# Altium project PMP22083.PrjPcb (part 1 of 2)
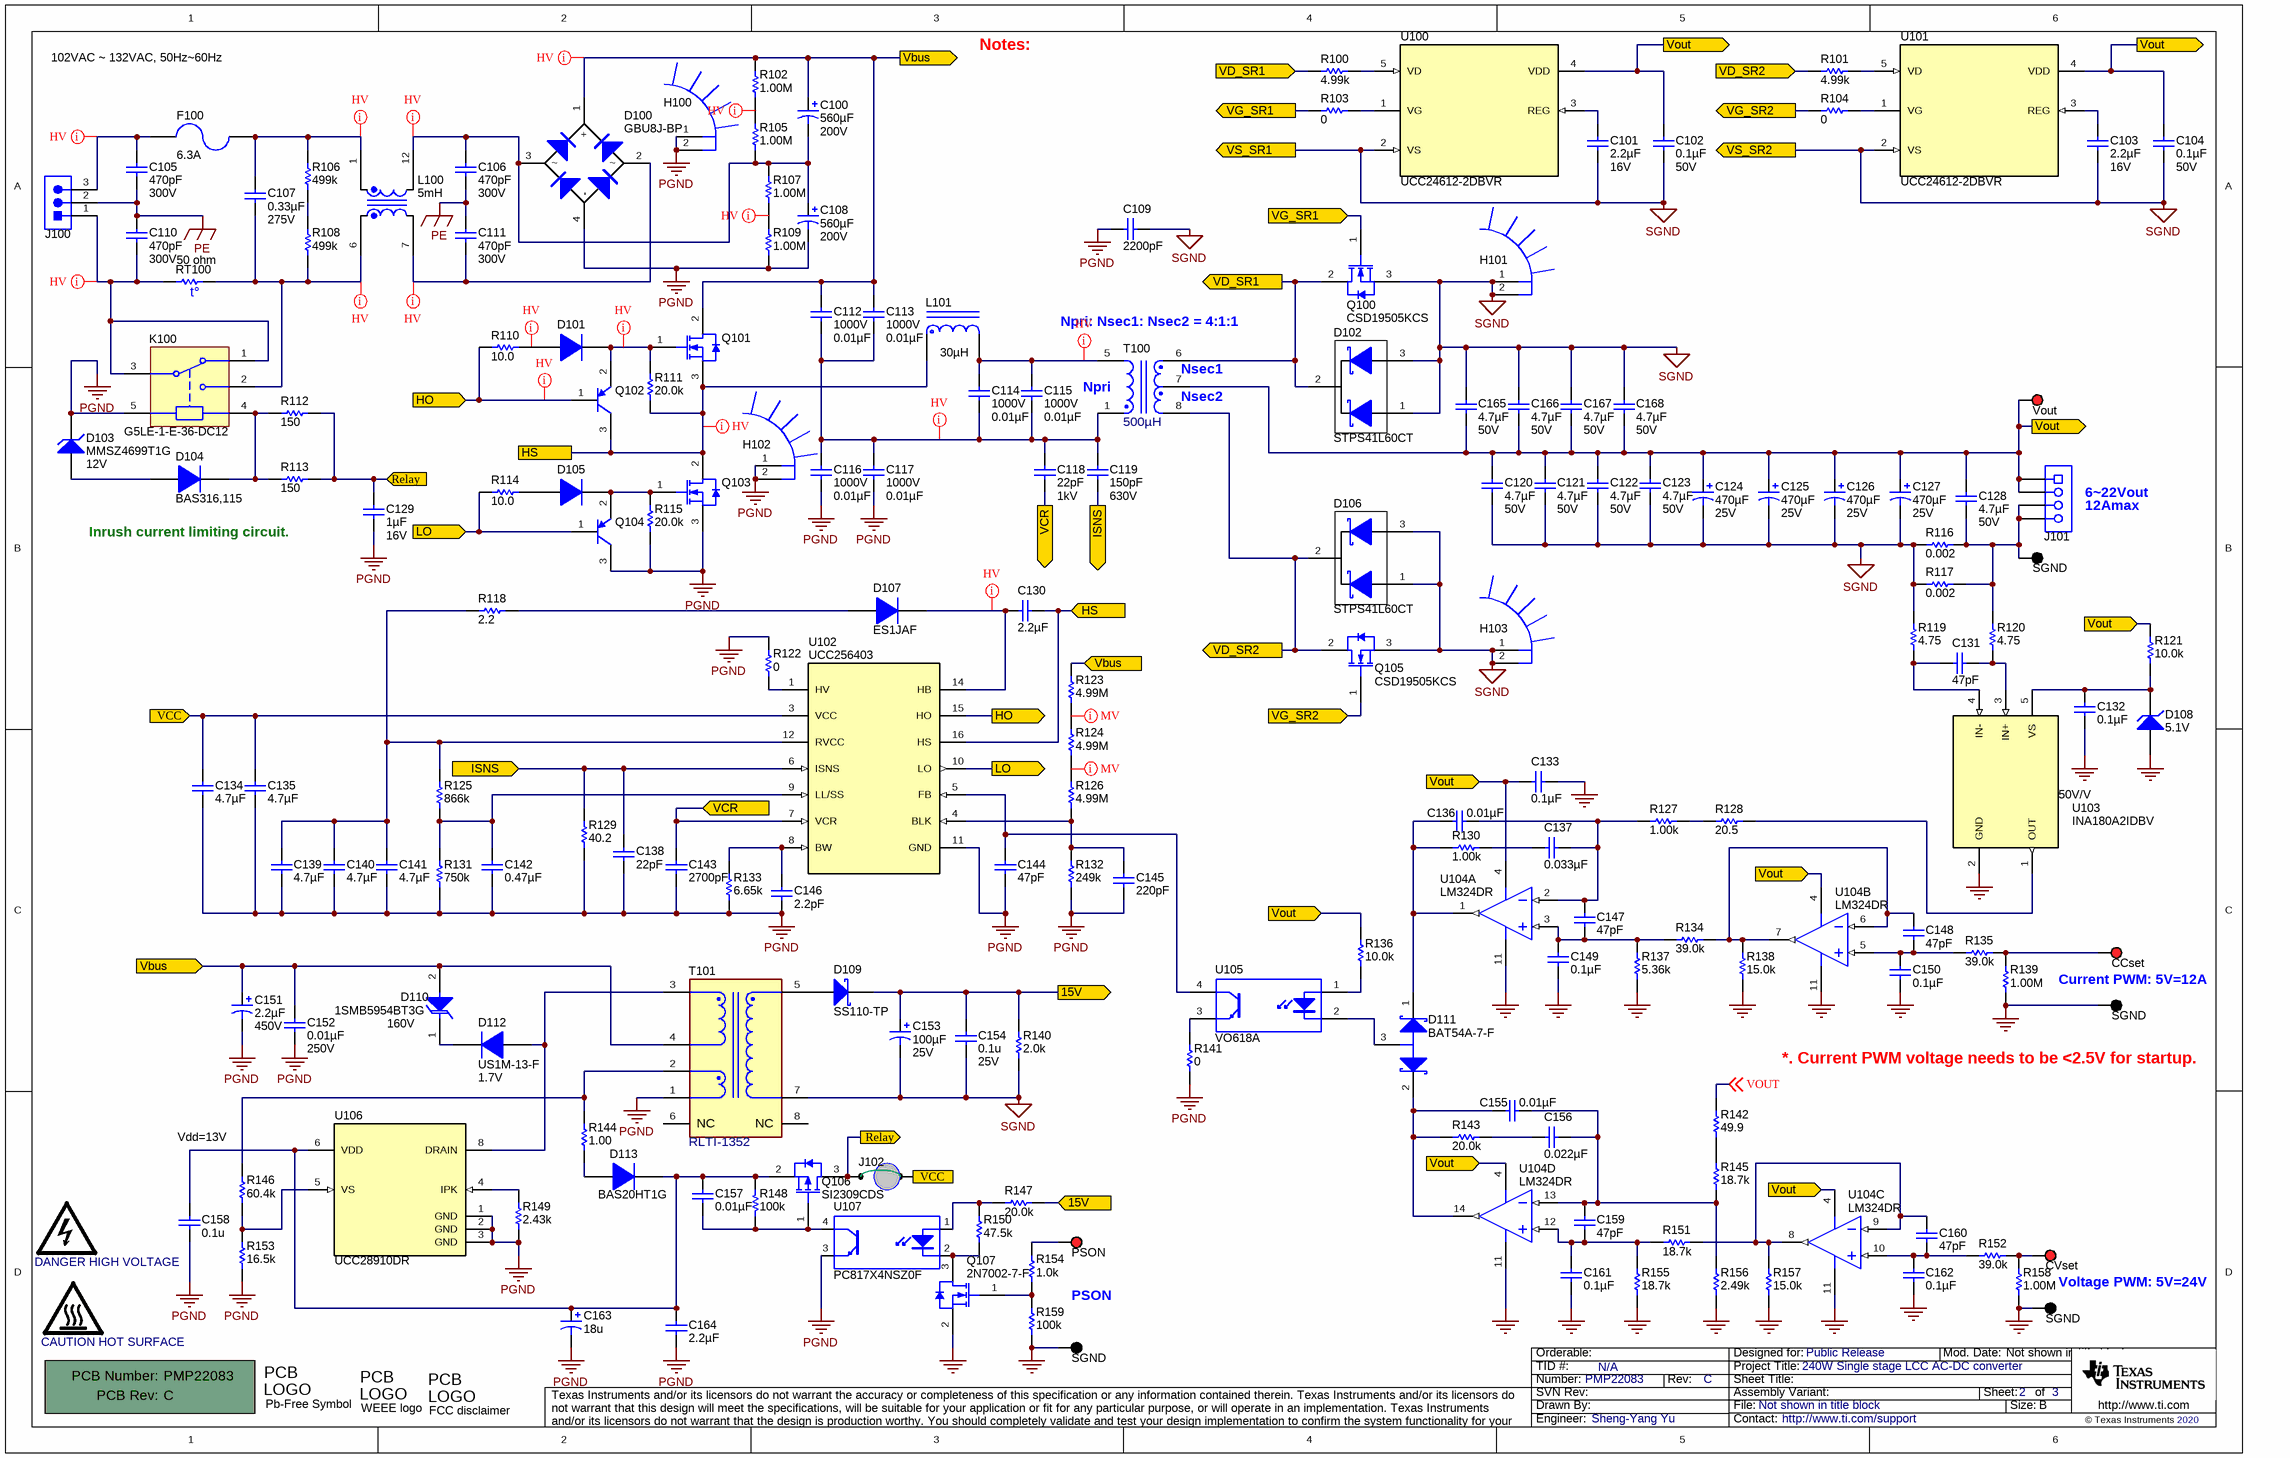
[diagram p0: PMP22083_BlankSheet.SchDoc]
CopyrightYear: 2020; PCB_Layout: Sheng-Yang Yu; PCB_Rev: C; PRJ_Customer: Public Release; PRJ_Engineer: Sheng-Yang Yu; PRJ_Number: PMP22083; PRJ_Title: 240W Single stage LCC AC-DC converter; SCH_Rev: C; TechSupport: http://www.ti.com/support; TID: N/A
1 sheet, 187 parts. Net scope: flat (ports and power ports of the same name join across sheets).
Board file: PMP22083_PCB.PcbDoc

## Sheet PMP22083_BlankSheet.SchDoc
size 431 x 279 mm; Date: Not shown in title block; ApprovedBy: Not shown in title block; CheckedBy: Not shown in title block; Author: Not shown in title block; CompanyName: Not shown in title block; Engineer: Not shown in title block; Organization: Not shown in title block; Address1: Not shown in title block; Address2: Not shown in title block; Address3: Not shown in title block; Address4: Not shown in title block; DocumentNumber: 1; Revision: Use project parameter SCH_Rev; SheetNumber: 2; SheetTotal: 3; PageSetup: Record=PageOptions¦CenterHorizontal=True¦CenterVertical=True¦PrintScale=1.00¦XCorrection=1.00¦YCorrection=1.00¦PrintKind=0¦BorderSize=5000000¦LeftOffset=0¦BottomOffset=0¦Orientation=2¦PaperLength=1000¦PaperWidth=1000¦Scale=100¦PaperSource=15¦PrintQuality=600¦MediaType=1¦DitherType=10¦PaperKind=Letter¦PrintScaleMode=1

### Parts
(Parts that share a designator on the sheet are numbered #1, #2 ... from top to bottom, then left to right.)
!PCB100  Printed Circuit Board  (value not drawn)  (mechanical)
C100  Cap_F: 560µF  VDC_V: 200V  [Nichicon_2200x3000_Snap]  (hidden comment: LLS2W101MELZ)
C101  ValueDisplayed: 2.2µF  Value2: 16V  [0603]  (hidden comment: 885012106018)
C102  ValueDisplayed: 0.1µF  Value2: 50V  [0603]  (hidden comment: 885012206095)
C103  ValueDisplayed: 2.2µF  Value2: 16V  [0603]  (hidden comment: 885012106018)
C104  ValueDisplayed: 0.1µF  Value2: 50V  [0603]  (hidden comment: 885012206095)
C105  ValueDisplayed: 470pF  Value2: 300V  [VY2_750x500]  (hidden comment: VY2471K29Y5SS63V7)
C106  ValueDisplayed: 470pF  Value2: 300V  [VY2_750x500]  (hidden comment: VY2471K29Y5SS63V7)
C107  ValueDisplayed: 0.33µF  Value2: 275V  [CAPRR1500W80L1750T950H1750]  (hidden comment: ECQ-U2A334ML)
C108  Cap_F: 560µF  VDC_V: 200V  [Nichicon_2200x3000_Snap]  (hidden comment: LLS2W101MELZ)
C109  ValueDisplayed: 2200pF  [AY2_950x500_Straight]  (hidden comment: AY2222M35Y5US63L7)
C110  ValueDisplayed: 470pF  Value2: 300V  [VY2_750x500]  (hidden comment: VY2471K29Y5SS63V7)
C111  ValueDisplayed: 470pF  Value2: 300V  [VY2_750x500]  (hidden comment: VY2471K29Y5SS63V7)
C112  VDC_V: 1000V  ValueDisplayed: 0.01µF  [B32621_1300x600x1200]  (hidden comment: B32671L0103J000)
C113  VDC_V: 1000V  ValueDisplayed: 0.01µF  [B32621_1300x600x1200]  (hidden comment: B32671L0103J000)
C114  VDC_V: 1000V  ValueDisplayed: 0.01µF  [B32621_1300x600x1200]  (hidden comment: B32671L0103J000)
C115  VDC_V: 1000V  ValueDisplayed: 0.01µF  [B32621_1300x600x1200]  (hidden comment: B32671L0103J000)
C116  VDC_V: 1000V  ValueDisplayed: 0.01µF  [B32621_1300x600x1200]  (hidden comment: B32671L0103J000)
C117  VDC_V: 1000V  ValueDisplayed: 0.01µF  [B32621_1300x600x1200]  (hidden comment: B32671L0103J000)
C118  ValueDisplayed: 22pF  Value2: 1kV  [1206]  (hidden comment: VJ1206A220JXGAT5Z)
C119  ValueDisplayed: 150pF  Value2: 630V  [1206]  (hidden comment: GRM31A5C2J151JW01D)
C120  ValueDisplayed: 4.7µF  Value2: 50V  [1206_190]  (hidden comment: UMK316AB7475KL-T)
C121  ValueDisplayed: 4.7µF  Value2: 50V  [1206_190]  (hidden comment: UMK316AB7475KL-T)
C122  ValueDisplayed: 4.7µF  Value2: 50V  [1206_190]  (hidden comment: UMK316AB7475KL-T)
C123  ValueDisplayed: 4.7µF  Value2: 50V  [1206_190]  (hidden comment: UMK316AB7475KL-T)
C124  ValueDisplayed: 470µF  Value2: 25V  [FR_1000x2000]  (hidden comment: 25SEK470M)
C125  ValueDisplayed: 470µF  Value2: 25V  [FR_1000x2000]  (hidden comment: 25SEK470M)
C126  ValueDisplayed: 470µF  Value2: 25V  [FR_1000x2000]  (hidden comment: 25SEK470M)
C127  ValueDisplayed: 470µF  Value2: 25V  [FR_1000x2000]  (hidden comment: 25SEK470M)
C128  ValueDisplayed: 4.7µF  Value2: 50V  [1206_190]  (hidden comment: UMK316AB7475KL-T)
C129  ValueDisplayed: 1µF  Value2: 16V  [0805_HV]  (hidden comment: 0805YD105KAT2A)
C130  ValueDisplayed: 2.2µF  [1206]  (hidden comment: C1206C225K4RACTU)
C131  ValueDisplayed: 47pF  [0603]  (hidden comment: C0603C470J5GACTU)
C132  ValueDisplayed: 0.1µF  [0402]  (hidden comment: GRM155R61E104KA87D)
C133  ValueDisplayed: 0.1µF  [1206]  (hidden comment: C1206C104K5RACTU)
C134  ValueDisplayed: 4.7µF  [0603]  (hidden comment: GRM188R61C475KAAJ)
C135  ValueDisplayed: 4.7µF  [0603]  (hidden comment: GRM188R61C475KAAJ)
C136  ValueDisplayed: 0.01µF  [0402]  (hidden comment: GRM155R71H103KA88D)
C137  ValueDisplayed: 0.033µF  [0402]  (hidden comment: GRM155R61C333KA01D)
C138  ValueDisplayed: 22pF  [0603]  (hidden comment: 06035A220JAT2A)
C139  ValueDisplayed: 4.7µF  [0603]  (hidden comment: GRM188R61C475KAAJ)
C140  ValueDisplayed: 4.7µF  [0603]  (hidden comment: GRM188R61C475KAAJ)
C141  ValueDisplayed: 4.7µF  [0603]  (hidden comment: GRM188R61C475KAAJ)
C142  ValueDisplayed: 0.47µF  [0603]  (hidden comment: C0603C474Z8VACTU)
C143  ValueDisplayed: 2700pF  [0603]  (hidden comment: GRM188R71E272KA01D)
C144  ValueDisplayed: 47pF  [0603]  (hidden comment: GRM1885C1H470FA01J)
C145  ValueDisplayed: 220pF  [0603]  (hidden comment: GRM188R71H221KA01D)
C146  ValueDisplayed: 2.2pF  [0603]  (hidden comment: 06035A2R2CAT2A)
C147  ValueDisplayed: 47pF  [0603]  (hidden comment: GRM1885C1H470JA01D)
C148  ValueDisplayed: 47pF  [0603]  (hidden comment: GRM1885C1H470JA01D)
C149  ValueDisplayed: 0.1µF  [0805_HV]  (hidden comment: 08053C104JAT2A)
C150  ValueDisplayed: 0.1µF  [0805_HV]  (hidden comment: 08053C104JAT2A)
C151  ValueDisplayed: 2.2µF  Value2: 450V  [CKE_800x1150]  (hidden comment: 225CKE450MJM)
C152  ValueDisplayed: 0.01µF  Value2: 250V  [1206]  (hidden comment: C1206C103KARACTU)
C153  ValueDisplayed: 100µF  Value2: 25V  [NHG_630x1120]  (hidden comment: ECA-1EHG101)
C154  ValueDisplayed: 0.1u  Value2: 25V  [0805_HV]  (hidden comment: 08053C104KAT2A)
C155  ValueDisplayed: 0.01µF  [0402]  (hidden comment: GRM155R71H103KA88D)
C156  ValueDisplayed: 0.022µF  [0402]  (hidden comment: GCM155R71H223KA55D)
C157  ValueDisplayed: 0.01µF  [0603]  (hidden comment: 885012206040)
C158  ValueDisplayed: 0.1u  [0603]  (hidden comment: 06035C104KAT2A)
C159  ValueDisplayed: 47pF  [0402]  (hidden comment: GRM1555C1H470JA01D)
C160  ValueDisplayed: 47pF  [0603]  (hidden comment: GRM1885C1H470JA01D)
C161  ValueDisplayed: 0.1µF  [0603]  (hidden comment: 06035C104KAT2A)
C162  ValueDisplayed: 0.1µF  [0603]  (hidden comment: 06035C104KAT2A)
C163  ValueDisplayed: 18u  [ML_500x500]  (hidden comment: 35ZL18MEFC5X7)
C164  ValueDisplayed: 2.2µF  [0603]  (hidden comment: GRM188R6YA225KA12D)
C165  ValueDisplayed: 4.7µF  Value2: 50V  [1206_190]  (hidden comment: UMK316AB7475KL-T)
C166  ValueDisplayed: 4.7µF  Value2: 50V  [1206_190]  (hidden comment: UMK316AB7475KL-T)
C167  ValueDisplayed: 4.7µF  Value2: 50V  [1206_190]  (hidden comment: UMK316AB7475KL-T)
C168  ValueDisplayed: 4.7µF  Value2: 50V  [1206_190]  (hidden comment: UMK316AB7475KL-T)
CCset  5000  [Keystone5000]  (value not drawn)
CVset  5000  [Keystone5000]  (value not drawn)
D100  GBU8J-BP  [GBU]
D101  MMDL914-TP  [SOD-323]  (value not drawn)
D102  STPS41L60CT  [TO-220AB]
D103  MMSZ4699T1G  value 12V  [SOD-123]
D104  BAS316,115  [sod-323]
D105  MMDL914-TP  [SOD-323]  (value not drawn)
D106  STPS41L60CT  [TO-220AB]
D107  ES1JAF  [SMAF]
D108  value 5.1V  [SOD-323]  (hidden comment: MMSZ5231BS-7-F)
D109  SS110-TP  [SMA]
D110  1SMB5954BT3G  value 160V  [SMB]
D111  BAT54A-7-F  [SOT-23]
D112  US1M-13-F  value 1.7V  [SMA]
D113  BAS20HT1G  [sod-323]
F100  Irating_A: 6.3A  [FUSE_372]  (hidden comment: 37216300001)
H100  532602B02500G  [Aavid_532602B02500G]  (value not drawn)
H101  513302B02500G  [531202]  (value not drawn)
H102  513302B02500G  [531202]  (value not drawn)
H103  513302B02500G  [531202]  (value not drawn)
J100  1-1318301-3  [TE_1-1318301-3]  (value not drawn)
J101  ED120/4DS  [On-Shore_ED120_4DS]  (value not drawn)
J102  923345-05-C  [923345-05-C]  (value not drawn)
K100  G5LE-1-E-36-DC12  [RELAY_875]
L100  ValueDisplayed: 5mH  [WE-CMB_XL]  (hidden comment: 744825605)
L101  Ind_H: 30µH  [FP-61219_SMT_36MM0_34MM0-MFG]  (hidden comment: 61219)
LOGO100  DANGER HIGH VOLTAGE  [IEC_HighVoltage_Small]  (no BOM)
LOGO101  CAUTION HOT SURFACE  [IEC_HotSurface_Small]  (no BOM)
Logo102  Pb-Free Symbol  [Pb-Free_Overlay_Medium]  (no BOM)
Logo103  WEEE logo  [WEEE_Minimum]  (no BOM)
Logo104  FCC disclaimer  [FCC_disclaimer]  (no BOM)
PSON  5000  [Keystone5000]  (value not drawn)
Q100  CSD19505KCS  [KCS0003B]
Q101  IPP60R090CFD7XKSA1  [TO-220FP]  (value not drawn)
Q102  FMMT718TA  [SOT-23]  (value not drawn)
Q103  IPP60R090CFD7XKSA1  [TO-220FP]  (value not drawn)
Q104  FMMT718TA  [SOT-23]  (value not drawn)
Q105  CSD19505KCS  [KCS0003B]
Q106  SI2309CDS  [SOT-23]
Q107  2N7002-7-F  [SOT-23]
R100  ValueDisplayed: 4.99k  [1206]  (hidden comment: CRCW12064K99FKEA)
R101  ValueDisplayed: 4.99k  [1206]  (hidden comment: CRCW12064K99FKEA)
R102  ValueDisplayed: 1.00M  [1206]  (hidden comment: CRCW12061M00FKEA)
R103  ValueDisplayed: 0  [0402]  (hidden comment: CRCW04020000Z0ED)
R104  ValueDisplayed: 0  [0402]  (hidden comment: CRCW04020000Z0ED)
R105  ValueDisplayed: 1.00M  [1206]  (hidden comment: CRCW12061M00FKEA)
R106  ValueDisplayed: 499k  [1206]  (hidden comment: CRCW1206499KFKEA)
R107  ValueDisplayed: 1.00M  [1206]  (hidden comment: CRCW12061M00FKEA)
R108  ValueDisplayed: 499k  [1206]  (hidden comment: CRCW1206499KFKEA)
R109  ValueDisplayed: 1.00M  [1206]  (hidden comment: CRCW12061M00FKEA)
R110  ValueDisplayed: 10.0  [0603]  (hidden comment: CRCW060310R0FKEA)
R111  ValueDisplayed: 20.0k  [0603]  (hidden comment: CRCW060320K0FKEA)
R112  ValueDisplayed: 150  [1206]  (hidden comment: CRCW1206150RJNEA)
R113  ValueDisplayed: 150  [1206]  (hidden comment: CRCW1206150RJNEA)
R114  ValueDisplayed: 10.0  [0603]  (hidden comment: CRCW060310R0FKEA)
R115  ValueDisplayed: 20.0k  [0603]  (hidden comment: CRCW060320K0FKEA)
R116  ValueDisplayed: 0.002  [2010]  (hidden comment: PMR50HZPFV2L00)
R117  ValueDisplayed: 0.002  [2010]  (hidden comment: PMR50HZPFV2L00)
R118  ValueDisplayed: 2.2  [0603]  (hidden comment: CRCW06032R20JNEA)
R119  ValueDisplayed: 4.75  [0603]  (hidden comment: RC0603FR-074R75L)
R120  ValueDisplayed: 4.75  [0603]  (hidden comment: RC0603FR-074R75L)
R121  ValueDisplayed: 10.0k  [0603]  (hidden comment: CRCW060310K0FKEA)
R122  ValueDisplayed: 0  [0603]  (hidden comment: CRCW06030000Z0EA)
R123  ValueDisplayed: 4.99M  [1206]  (hidden comment: CRCW12064M99FKEA)
R124  ValueDisplayed: 4.99M  [1206]  (hidden comment: CRCW12064M99FKEA)
R125  ValueDisplayed: 866k  [1206]  (hidden comment: CRCW1206866KFKEA)
R126  ValueDisplayed: 4.99M  [1206]  (hidden comment: CRCW12064M99FKEA)
R127  ValueDisplayed: 1.00k  [1206]  (hidden comment: CRCW12061K00FKEA)
R128  ValueDisplayed: 20.5  [1206]  (hidden comment: CRCW120620R5FKEA)
R129  ValueDisplayed: 40.2  [0603]  (hidden comment: CRCW060340R2FKEA)
R130  ValueDisplayed: 1.00k  [0402]  (hidden comment: CRCW04021K00FKED)
R131  ValueDisplayed: 750k  [0603]  (hidden comment: CRCW0603750KFKEA)
R132  ValueDisplayed: 249k  [0603]  (hidden comment: CRCW0603249KFKEA)
R133  ValueDisplayed: 6.65k  [0603]  (hidden comment: CRCW06036K65FKEA)
R134  ValueDisplayed: 39.0k  [0603]  (hidden comment: RC0603FR-0739KL)
R135  ValueDisplayed: 39.0k  [0603]  (hidden comment: RC0603FR-0739KL)
R136  ValueDisplayed: 10.0k  [0805_HV]  (hidden comment: CRCW080510K0FKEA)
R137  ValueDisplayed: 5.36k  [0603]  (hidden comment: CRCW06035K36FKEA)
R138  ValueDisplayed: 15.0k  [0603]  (hidden comment: CRCW060315K0FKEA)
R139  ValueDisplayed: 1.00M  [0603]  (hidden comment: CRCW06031M00FKEA)
R140  value 2.0k  [0603]  (hidden comment: CRCW06032K00JNEA)
R141  ValueDisplayed: 0  [1206]  (hidden comment: CRCW12060000Z0EA)
R142  ValueDisplayed: 49.9  [1206]  (hidden comment: RC1206FR-0749R9L)
R143  ValueDisplayed: 20.0k  [0402]  (hidden comment: CRCW040220K0FKED)
R144  value 1.00  [0603]  (hidden comment: RC0603FR-071RL)
R145  ValueDisplayed: 18.7k  [0603]  (hidden comment: CRCW060318K7FKEA)
R146  value 60.4k  [0603]  (hidden comment: CRCW060360K4FKEA)
R147  ValueDisplayed: 20.0k  [1206]  (hidden comment: CRCW120620K0FKEA)
R148  ValueDisplayed: 100k  [0603]  (hidden comment: CRCW0603100KFKEA)
R149  value 2.43k  [0603]  (hidden comment: CRCW06032K43FKEA)
R150  ValueDisplayed: 47.5k  [0603]  (hidden comment: ERJ-3EKF4752V)
R151  ValueDisplayed: 18.7k  [0603]  (hidden comment: CRCW060318K7FKEA)
R152  ValueDisplayed: 39.0k  [1206]  (hidden comment: ERJ-8ENF3902V)
R153  value 16.5k  [0603]  (hidden comment: CRCW060316K5FKEA)
R154  ValueDisplayed: 1.0k  [0603]  (hidden comment: CRCW06031K00JNEA)
R155  ValueDisplayed: 18.7k  [0603]  (hidden comment: CRCW060318K7FKEA)
R156  ValueDisplayed: 2.49k  [0603]  (hidden comment: RC0603FR-072K49L)
R157  ValueDisplayed: 15.0k  [0603]  (hidden comment: CRCW060315K0FKEA)
R158  ValueDisplayed: 1.00M  [0603]  (hidden comment: CRCW06031M00FKEA)
R159  ValueDisplayed: 100k  [0603]  (hidden comment: CRCW0603100KFKEA)
RT100  value 50 ohm  [TDK_B751]  (hidden comment: B59751B0120A070)
SGND#1  5001  [Keystone5001]  (value not drawn)
SGND#2  5001  [Keystone5001]  (value not drawn)
SGND#3  5001  [Keystone5001]  (value not drawn)
SGND#4  5001  [Keystone5001]  (value not drawn)
T100  500µH  [FP-61201_SMT_XFRMR_44MM0_34MM0-MFG]
T101  RLTI-1352  [FP-RLTI-1352_PTH_XFRMR_0IN42_0IN48-MFG]
U100  PartNumber: UCC24612-2DBVR  [DBV0005A_N]  (hidden comment: UCC24612-1DBVR)
U101  PartNumber: UCC24612-2DBVR  [DBV0005A_N]  (hidden comment: UCC24612-1DBVR)
U102  UCC256403  [DDB0014A]
U103  INA180A2IDBV  [DBV0005A_N]
U104  LM324DR  [D0014A_N]  (parts A,B,C,D of 4)
U105  VO618A  [DIP-4]
U106  UCC28910DR  [D0007A_N]
U107  PC817X4NSZ0F  [DIP762W60P254L460H350Q4B]
Vout  5000  [Keystone5000]  (value not drawn)

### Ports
15V (in), 15V (out), HO (in), HO (out), HS, HS (in), ISNS (in), ISNS (out), LO (in), LO (out), Relay (in), Relay (out), Vbus (in), Vbus (out), VCC (in), VCC (out), VCR (in), VCR (out), VD_SR1 (in), VD_SR1 (out), VD_SR2 (in), VD_SR2 (out), VG_SR1 (in), VG_SR1 (out), VG_SR2 (in), VG_SR2 (out), Vout (in), Vout (out), VS_SR1 (out), VS_SR2 (out)

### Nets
PE: C105.1 C106.1 C110.2 C111.2 J100.2
PGND: C108.2(-) C109.2 C116.2 C117.2 C129.1 C134.1 C135.1 C138.2 C139.2 C140.2 C141.2 C142.2 C143.2 C144.2 C145.2 C146.2 C151.2(-) C152.2 C158.2 C163.2(-) C164.1 D100.4(-) D103.1(K) H100.1 H100.2 H102.1 H102.2 K100.5 Q103.3(S) Q104.3(C) R109.1 R115.1 R122.2 R129.1 R131.1 R132.1 R133.1 R141.1 R149.1 R153.1 T101.1 U102.11(GND) U106.1(GND) U106.2(GND) U106.3(GND) U107.3(E)
SGND: C101.2 C102.2 C103.2 C104.2 C109.1 C120.2 C121.2 C122.2 C123.2 C124.2(-) C125.2(-) C126.2(-) C127.2(-) C132.2 C133.1 C149.2 C150.2 C153.2(-) C154.2 C161.2 C162.2 C165.1 C166.1 C167.1 C168.1 D102.1(A) D102.3(A) D106.1(A) D106.3(A) D108.2(A) H101.1 H101.2 H103.1 H103.2 Q100.3(S) Q105.3(S) Q107.2(S) R116.1 R117.1 R119.2 R137.1 R138.1 R139.1 R140.1 R155.1 R156.1 R157.1 R158.1 R159.1 SGND#2.1 SGND#3.1 SGND#4.1 T101.7 U100.2(VS) U101.2(VS) U103.2(GND) U104.11(GND) ; port VS_SR1, port VS_SR2
15V: C153.1(+) C154.1 D109.1(K) R140.2 R147.1 ; port 15V
HO: Q102.1(B) R110.1 U102.15(HO) ; port HO
HS: C130.2 L101.1 Q101.3(S) Q102.3(C) Q103.2(D) R111.1 U102.16(HS) ; port HS
ISNS: C119.1 C138.1 R129.2 U102.6(ISNS) ; port ISNS
LO: Q104.1(B) R114.1 U102.10(LO) ; port LO
Relay: C129.2 J102.1 Q106.3(D) R112.2 R113.2 ; port Relay
Vbus: C100.1(+) C112.1 C113.1 C151.1(+) C152.1 D100.1(+) D110.2(A) Q101.2(D) R102.2 R123.2 T101.4 ; port Vbus
VCC: C134.2 C135.2 J102.2 U102.3(VCC) ; port VCC
VCR: C118.2 C143.1 U102.7(VCR) ; port VCR
VD_SR1: D102.2(K) Q100.2(D) R100.1 T100.6 ; port VD_SR1
VD_SR2: D106.2(K) Q105.2(D) R101.1 T100.8 ; port VD_SR2
VG_SR1: Q100.1(G) R103.1 ; port VG_SR1
VG_SR2: Q105.1(G) R104.1 ; port VG_SR2
Vout: C102.1 C104.1 C120.1 C121.1 C122.1 C123.1 C124.1(+) C125.1(+) C126.1(+) C127.1(+) C128.1 C133.2 C165.2 C166.2 C167.2 C168.2 J101.1 J101.2 R121.2 R136.2 T100.7 U100.4(VDD) U101.4(VDD) U104.4(V+) Vout.1 ; port Vout
VOUT: R142.2 ; off-sheet VOUT  [a separate net that carries the same name]
NetC100_2: C100.2(-) C106.2 C108.1(+) D100.3 L100.12 R105.1 R107.2
NetC101_1: C101.1 U100.3(REG)
NetC103_1: C103.1 U101.3(REG)
NetC105_2: C105.2 F100.1 J100.3
NetC107_1: C107.1 K100.2 L100.6 R108.1 RT100.2
NetC107_2: C107.2 F100.2 L100.1 R106.2
NetC110_1: C110.1 J100.1 K100.1 K100.3 RT100.1
NetC111_1: C111.1 D100.2 L100.7
NetC112_2: C112.2 C113.2 C114.2 C115.2 C116.1 C117.1 C118.1 C119.2 T100.1
NetC114_1: C114.1 C115.1 L101.2 T100.5
NetC128_2: C128.2 J101.3 J101.4 R116.2 R117.2 R120.2 SGND#1.1
NetC130_1: C130.1 D107.1(K) U102.14(HB)
NetC131_1: C131.1 R120.1 U103.3(IN+)
NetC131_2: C131.2 R119.1 U103.4(IN-)
NetC132_1: C132.1 D108.1(K) R121.1 U103.5(VS)
NetC136_1: C136.1 D111.1(K1) R130.1 U104.1(OUT1)
NetC136_2: C136.2 C137.1 C147.1 R127.1 U104.2(IN1-)
NetC137_2: C137.2 R130.2
NetC139_1: C139.1 C140.1 C141.1 R118.1 R125.2 U102.12(RVCC)
NetC142_1: C142.1 R125.1 R131.2 U102.9(LL/SS)
NetC144_1: C144.1 U102.5(FB) U105.4(C)
NetC145_1: C145.1 R126.1 R132.2 U102.4(BLK)
NetC146_1: C146.1 R133.2 U102.8(BW)
NetC147_2: C147.2 C149.1 R134.1 R137.2 U104.3(IN1+)
NetC148_1: C148.1 R134.2 R138.2 U104.6(IN2-) U104.7(OUT2)
NetC148_2: C148.2 C150.1 R135.1 U104.5(IN2+)
NetC155_1: C155.1 D111.2(K2) R143.1 U104.14(OUT4)
NetC155_2: C155.2 C156.1 C159.1 R145.1 R156.2 U104.13(IN4-)
NetC156_2: C156.2 R143.2
NetC157_1: C157.1 C158.1 C163.1(+) C164.2 D113.1(K) Q106.2(S) R148.2 U106.6(VDD)
NetC157_2: C157.2 Q106.1(G) R148.1 U107.4(C)
NetC159_2: C159.2 C161.1 R151.2 R155.2 U104.12(IN4+)
NetC160_1: C160.1 R151.1 R157.2 U104.8(OUT3) U104.9(IN3-)
NetC160_2: C160.2 C162.1 R152.1 U104.10(IN3+)
NetCCset_1: CCset.1 R135.2 R139.2
NetCVset_1: CVset.1 R152.2 R158.2
NetD101_1: D101.1(K) Q101.1(G) Q102.2(E) R111.2
NetD101_2: D101.2(A) R110.2
NetD103_2: D103.2(A) D104.2(A)
NetD104_1: D104.1(K) K100.4 R112.1 R113.1
NetD105_1: D105.1(K) Q103.1(G) Q104.2(E) R115.2
NetD105_2: D105.2(A) R114.2
NetD107_2: D107.2(A) R118.2
NetD109_2: D109.2(A) T101.5
NetD110_1: D110.1(K) D112.1(K)
NetD111_3: D111.3(A) U105.2(K)
NetD112_2: D112.2(A) T101.3 U106.8(DRAIN)
NetD113_2: D113.2(A) R144.1
NetPSON_1: PSON.1 R154.2
NetQ107_1: Q107.1(G) R154.1 R159.2
NetQ107_3: Q107.3(D) R150.1 U107.2(K)
NetR100_2: R100.2 U100.5(VD)
NetR101_2: R101.2 U101.5(VD)
NetR102_1: R102.1 R105.2
NetR103_2: R103.2 U100.1(VG)
NetR104_2: R104.2 U101.1(VG)
NetR106_1: R106.1 R108.2
NetR107_1: R107.1 R109.2
NetR122_1: R122.1 U102.1(HV)
NetR123_1: R123.1 R124.2
NetR124_1: R124.1 R126.2
NetR127_2: R127.2 R128.1
NetR128_2: R128.2 U103.1(OUT)
NetR136_1: R136.1 U105.1(A)
NetR141_2: R141.2 U105.3(E)
NetR142_1: R142.1 R145.2
NetR144_2: R144.2 R146.2 T101.2
NetR146_1: R146.1 R153.2 U106.5(VS)
NetR147_2: R147.2 R150.2 U107.1(A)
NetR149_2: R149.2 U106.4(IPK)

Not connected (* = marked no-connect by the designer): T101 6(NC) 8(NC)

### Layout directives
net class HV: HO, HS, NetC100_2, NetC105_2, NetC107_1, NetC107_2, NetC110_1, NetC111_1, NetC112_2, NetC114_1, NetC130_1, NetD101_1, NetD101_2, NetR102_1, NetR107_1, Vbus
net class MV: NetR123_1, NetR124_1

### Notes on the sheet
- 102VAC ~ 132VAC, 50Hz~60Hz
- Notes:
- (near T100) Npri: Nsec1: Nsec2 = 4:1:1
- (near T100) Npri
- (near T100) Nsec1
- (near T100) Nsec2
- (near J101) 6|2Vout
- Inrush current limiting circuit.
- (near J101) 12Amax
- (near U103) 50V/V
- Current PWM: 5V=12A
- *. Current PWM voltage needs to be <2.5V for startup.
- (near R146) Vdd=13V
- Voltage PWM: 5V=24V
- PSON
